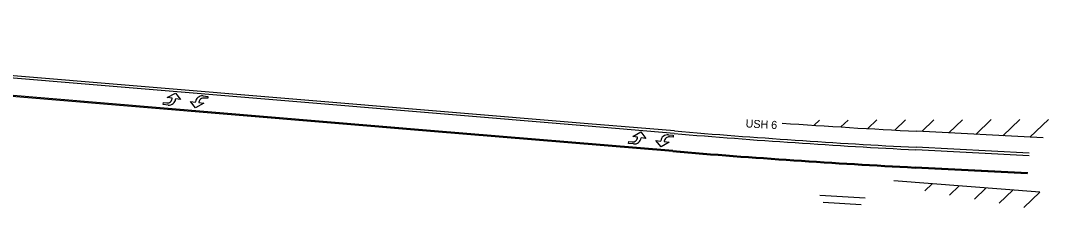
# Model space of a CAD drawing. Extents: x 20499978 to 20505524, y 7953342 to 7954320.
# Drawn here: x 20503940 to 20504711, y 7953618 to 7953758 of the extents above; entities that cross this region are included whole.
import ezdxf

# ---------------------------------------------------------------- set-up
doc = ezdxf.new("R2010")
doc.units = 0
for name, color, linetype in [('EdgePaved', 7, 'Continuous'), ('Entrance', 7, 'Continuous'), ('UtilitiesBelowGround', 7, 'Continuous')]:
    doc.layers.add(name, color=color, linetype=linetype)

msp = doc.modelspace()

# ---------------------------------------------------------------- linework, layer by layer
at = {"layer": 'EdgePaved'}
for p, q in [((20504365.67, 7953680.54), (20503441.01, 7953757.69)), ((20504676.42, 7953671.59), (20504689.11, 7953683.72)), ((20504696.69, 7953670.54), (20504710.55, 7953683.79)), ((20504430.24, 7953675.15), (20504365.67, 7953680.54)), ((20504535, 7953679.4), (20504539.01, 7953683.23)), ((20504555.04, 7953678.13), (20504560.45, 7953683.3)), ((20504575.16, 7953676.93), (20504581.89, 7953683.37)), ((20504595.34, 7953675.79), (20504603.34, 7953683.44)), ((20504615.59, 7953674.72), (20504624.78, 7953683.51)), ((20504635.87, 7953673.68), (20504646.22, 7953683.58)), ((20504656.14, 7953672.63), (20504667.67, 7953683.65)), ((20504706.49, 7953670.04), (20504611.99, 7953674.91)), ((20504696.09, 7953656.64), (20504611.28, 7953661.01)), ((20504696.19, 7953658.55), (20504611.37, 7953662.93)), ((20504694.92, 7953643.1), (20504610.58, 7953647.45)), ((20504695.18, 7953643.84), (20504610.61, 7953648.2)), ((20504704.11, 7953629.35), (20504594.68, 7953637.77)), ((20504617.87, 7953630.35), (20504623.32, 7953635.56)), ((20504636.46, 7953627.26), (20504643.52, 7953634.01)), ((20504655.05, 7953624.17), (20504663.71, 7953632.45)), ((20504673.64, 7953621.08), (20504683.91, 7953630.9)), ((20504573.3, 7953624.81), (20504539.15, 7953626.77)), ((20504692.23, 7953617.99), (20504704.11, 7953629.35)), ((20504570.16, 7953619.98), (20504541.62, 7953621.62))]:
    msp.add_line(p, q, dxfattribs=at)
for points in [[(20504428.95, 7953659.7), (20504247.31, 7953674.86), (20503288.17, 7953754.9)], [(20504430.08, 7953673.24), (20504365.51, 7953678.63), (20503440.85, 7953755.78)], [(20504429.02, 7953660.45), (20504247.38, 7953675.6), (20503439.75, 7953743)]]:
    msp.add_lwpolyline(points, dxfattribs=at)
for radius, start in [(5710.25, 266.03323), (5724.17, 265.23083), (5722.25, 265.23083), (5737.75, 265.230833), (5737, 265.230833)]:
    msp.add_arc((20504906, 7959377.59), radius, start, 267.04866, dxfattribs=at)
at = {"layer": 'Entrance'}
for p, q in [((20504053.79, 7953699.26), (20504053.82, 7953699.57)), ((20504056.42, 7953699.21), (20504056.41, 7953699.03)), ((20504071.24, 7953696.68), (20504071.26, 7953696.86)), ((20504073.88, 7953696.63), (20504073.85, 7953696.32)), ((20504402.58, 7953670.15), (20504402.6, 7953670.46)), ((20504405.21, 7953670.1), (20504405.19, 7953669.92)), ((20504420.03, 7953667.57), (20504420.05, 7953667.75)), ((20504422.66, 7953667.53), (20504422.64, 7953667.21))]:
    msp.add_line(p, q, dxfattribs=at)
for points in [[(20504053.82, 7953699.57), (20504050.17, 7953700.07), (20504056.27, 7953703.54)], [(20504053.82, 7953699.57), (20504050.17, 7953700.07), (20504056.27, 7953703.54)], [(20504053.79, 7953699.26), (20504053.82, 7953699.57)], [(20504056.27, 7953703.54), (20504060.07, 7953698.71), (20504056.42, 7953699.21)], [(20504056.27, 7953703.54), (20504060.07, 7953698.71), (20504056.42, 7953699.21)], [(20504056.42, 7953699.21), (20504056.41, 7953699.03)], [(20504076.93, 7953701.37), (20504080.59, 7953701.05), (20504080.46, 7953699.56), (20504077.84, 7953699.79)], [(20504076.93, 7953701.37), (20504080.59, 7953701.05), (20504080.46, 7953699.56), (20504077.84, 7953699.79)], [(20504050.74, 7953694.52), (20504047.07, 7953694.84), (20504047.2, 7953696.33), (20504049.82, 7953696.1)], [(20504050.74, 7953694.52), (20504047.07, 7953694.84), (20504047.2, 7953696.33), (20504049.82, 7953696.1)], [(20504071.39, 7953692.35), (20504067.59, 7953697.18), (20504071.24, 7953696.68)], [(20504071.39, 7953692.35), (20504067.59, 7953697.18), (20504071.24, 7953696.68)], [(20504071.24, 7953696.68), (20504071.26, 7953696.86)], [(20504073.85, 7953696.32), (20504077.5, 7953695.82), (20504071.39, 7953692.35)], [(20504073.85, 7953696.32), (20504077.5, 7953695.82), (20504071.39, 7953692.35)], [(20504073.88, 7953696.63), (20504073.85, 7953696.32)], [(20504402.6, 7953670.46), (20504398.95, 7953670.96), (20504405.06, 7953674.43)], [(20504402.6, 7953670.46), (20504398.95, 7953670.96), (20504405.06, 7953674.43)], [(20504402.58, 7953670.15), (20504402.6, 7953670.46)], [(20504405.06, 7953674.43), (20504408.86, 7953669.6), (20504405.21, 7953670.1)], [(20504405.06, 7953674.43), (20504408.86, 7953669.6), (20504405.21, 7953670.1)], [(20504405.21, 7953670.1), (20504405.19, 7953669.92)], [(20504425.71, 7953672.26), (20504429.38, 7953671.94), (20504429.25, 7953670.45), (20504426.63, 7953670.68)], [(20504425.71, 7953672.26), (20504429.38, 7953671.94), (20504429.25, 7953670.45), (20504426.63, 7953670.68)], [(20504399.53, 7953665.42), (20504395.86, 7953665.73), (20504395.99, 7953667.22), (20504398.61, 7953666.99)], [(20504399.53, 7953665.42), (20504395.86, 7953665.73), (20504395.99, 7953667.22), (20504398.61, 7953666.99)], [(20504420.18, 7953663.24), (20504416.38, 7953668.07), (20504420.03, 7953667.57)], [(20504420.18, 7953663.24), (20504416.38, 7953668.07), (20504420.03, 7953667.57)], [(20504420.03, 7953667.57), (20504420.05, 7953667.75)], [(20504422.64, 7953667.21), (20504426.29, 7953666.71), (20504420.18, 7953663.24)], [(20504422.64, 7953667.21), (20504426.29, 7953666.71), (20504420.18, 7953663.24)], [(20504422.66, 7953667.53), (20504422.64, 7953667.21)]]:
    msp.add_lwpolyline(points, dxfattribs=at)
for centre, major_axis in [((20504050.12, 7953699.57), (-3.67, 0.32)), ((20504050.12, 7953699.57), (-3.67, 0.32)), ((20504076.5, 7953696.41), (5.24, -0.46)), ((20504076.5, 7953696.41), (5.24, -0.46)), ((20504077.54, 7953696.32), (3.67, -0.32)), ((20504077.54, 7953696.32), (3.67, -0.32)), ((20504051.17, 7953699.48), (-5.24, 0.46)), ((20504051.17, 7953699.48), (-5.24, 0.46)), ((20504398.91, 7953670.47), (-3.67, 0.32)), ((20504398.91, 7953670.47), (-3.67, 0.32)), ((20504399.96, 7953670.38), (-5.24, 0.46)), ((20504399.96, 7953670.38), (-5.24, 0.46)), ((20504425.28, 7953667.3), (5.24, -0.46)), ((20504425.28, 7953667.3), (5.24, -0.46)), ((20504426.33, 7953667.21), (3.67, -0.32)), ((20504426.33, 7953667.21), (3.67, -0.32))]:
    msp.add_ellipse(centre, major_axis=major_axis, ratio=0.9474, start_param=1.570796, end_param=3.141593, dxfattribs=at)

# ---------------------------------------------------------------- texts
at = {"layer": 'UtilitiesBelowGround'}
msp.add_text('USH 6', height=6, rotation=356.90003, dxfattribs=at).set_placement((20504483.48, 7953677.85))

doc.saveas('drawing.dxf')
